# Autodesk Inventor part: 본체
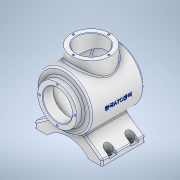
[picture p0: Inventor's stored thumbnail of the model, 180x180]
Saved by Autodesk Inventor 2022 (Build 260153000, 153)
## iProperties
Created: 2023-04
Part Number: 본체
Material: 알루미늄 6061
Document SubType Name: Modeling
Designer: Admin
Mass: 1291.94 g
Surface Area: 1063.05 cm^2
Volume: 478.495 cm^3
Density: 2.7 g/cm^3
Appearance: 알루미늄 - 평지
Author: Admin
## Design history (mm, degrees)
sketch "스케치2"
  geometry: L1 (-86.8, 0)-(86.8, 0) reference; L2 (0, -57.515)-(0, 99.419) reference; L3 (62, 0)-(62, 10); L4 (62, 10)-(23.355, 37.06); L5 (23.355, 37.06)-(23.355, 77); L6 (23.355, 77)-(-23.355, 77); L7 (-23.355, 77)-(-23.355, 37.06); L8 (-23.355, 37.06)-(-62, 10); L9 (-62, 10)-(-62, 0); L10 (-38.5, 0)-(38.5, 0); L11 (0, 0)-(0, 17); L12 (-62, 0)-(62, 0); A1 r 52.096 centre (0, -35.096) between (38.5, 0) and (-38.5, 0); 2 further points
  constraints: 20 end point, 4 symmetric about line, 3 perpendicular, 3 point on circle, 3 point on line, 1 centre point, 1 collinear, 1 horizontal, 1 midpoint, 1 parallel, 1 vertical
  dimensions: "d0" = 55 deg angle of L3 L4; "d1" = 10 distance of L3.start L3.end; "d2" = 124 distance between parallel lines of L3 L9; "d3" = 77 distance of L10.start L10.end; "d4" = 17 distance of L11.start L11.end; "d5" = 77 distance between parallel lines of L10 L6
extrude "돌출1" new body sketch "스케치2" stored distance "d6" = 80; taper "d7" = 0 deg
sketch "스케치3"
  geometry: L1 (77, 72.343)-(77, -93.292); L2 (0, -40)-(0, 40) reference; L3 (77, 48)-(127, 48); L4 (127, 48)-(127, -60); L5 (127, -60)-(77, -60); L6 (77, 48)-(77, -60); L7 (77, 40)-(37.06, 40) reference; L8 (-25.534, 0)-(153.205, 0) reference; L9 (77, 48)-(113, 48); L10 (113, 48)-(113, 60); L11 (113, 60)-(77, 60); L12 (77, 60)-(77, 48); L13 (0, 40)-(10, 40) reference; A1 r 113 centre (77, 53) between (77, -60) and (127, -48.336); 2 further points
  constraints: 18 end point, 4 point on line, 3 perpendicular, 2 horizontal, 2 parallel, 2 point on circle, 1 centre point, 1 collinear, 1 tangent, 1 vertical
  dimensions: "d8" = 77 distance between parallel lines of L2 L1; "d10" = 108 distance between parallel lines of L3 L5; "d12" = 226 diameter of A1; "d13" = 100 diameter of L4 L1; "d19" = 120 distance between parallel lines of L5 L11; "d20" = 72 diameter of L10 L1; "d21" = 20 distance between parallel lines of L13 L11
revolve "회전1" sketch "스케치3" stored, may be unused: angle "d14" = 360 deg
sketch "스케치6"
  geometry: L1 (77, 94.531)-(77, -106.028); L2 (0, -40)-(0, 40) reference; L3 (77, -53)-(120, -53); L4 (120, -53)-(120, 41); L5 (120, 41)-(77, 41); L6 (77, 41)-(77, -53); L7 (41, 60)-(113, 60) reference; L8 (77, 41)-(104, 41); L9 (104, 41)-(104, 60); L10 (104, 60)-(77, 60); L11 (77, 60)-(77, 41); A1 r 113 centre (77, 60) between (77, -53) and (120, -44.499); 3 further points
  constraints: 18 end point, 4 parallel, 3 point on line, 2 horizontal, 2 perpendicular, 2 point on circle, 1 centre point, 1 tangent, 1 vertical
  dimensions: "d22" = 77 distance between parallel lines of L2 L1; "d23" = 19 distance between parallel lines of L7 L5; "d24" = 54 diameter of L9.end L1; "d25" = 86 diameter of L4.end L1; "d27" = 113 distance between parallel lines of L7 L3; "d28" = 226 diameter of A1
revolve "회전2" sketch "스케치6" stored, may be unused: angle "d29" = 90 deg
node "작업 평면1"
sketch "스케치7"
  geometry: L1 (0, -57.6)-(0, 79.6) reference; L2 (50.4, 0)-(-50.4, 0) reference; L3 (-36, 60)-(36, 60) reference; C1 r 36 at (0, -2); 1 further point
  constraints: 1 centre point, 1 point on line
  dimensions: "d80" = 72 diameter of C1; "d81" = 62 distance from line of L3 C1.centre
extrude "돌출3" join sketch "스케치7" stored distance "d32" = 12; taper "d33" = 0 deg
sketch "스케치9"
  geometry: A1 r 32.5 centre (0, 0) between (0, 32.5) and (32.5, 0); 3 further points
  constraints: 4 point on circle, 1 centre point
  dimensions: "d37" = 65 diameter of A1
hole "구멍1" sketch "스케치9" at (0, 32.5), (32.5, 0), (0, -32.5), (-32.5, 0) diameter "d38" = 3.45873; stored, may be unused: countersink angle "d42" = 90 deg, drill point angle "d44" = 118 deg; dims "d39" = 8, "d40" = 4, "d41" = 2, "d43" = 10
node "작업 평면2"
sketch "스케치11"
  geometry: L1 (12.4, 0)-(-74.4, 0) reference; L2 (0, -56)-(0, 56) reference; L3 (-62, -40)-(-62, 40) reference; L4 (-62, 27)-(-54, 27); L5 (-54, 27)-(-54, 13); L6 (-54, 13)-(-62, 13); L7 (-62, 13)-(-62, 27); L8 (-62, -13)-(-54, -13); L9 (-54, -13)-(-54, -27); L10 (-54, -27)-(-62, -27); L11 (-62, -27)-(-62, -13); L12 (-62, -40)-(-38.5, -40) reference; 7 further points
  constraints: 16 end point, 4 parallel, 2 horizontal, 2 midpoint, 2 perpendicular, 2 point on line, 2 symmetric about line, 6 other
  dimensions: "d54" = 14 distance of L8.end L9.end; "d55" = 8 distance from line of L3 point (-54, -20); "d56" = 20 distance from line of L12 point (-54, -20)
extrude "돌출5" cut sketch "스케치11" distance "d57" = 20; taper "d58" = 0 deg
sketch "스케치14"
  geometry: L1 (-38.5, -96)-(-38.5, 16) reference; L2 (-125.3, -40)-(48.3, -40) reference; 5 further points
  constraints: 3 symmetric about line
  dimensions: "d59" = 108 distance of point (-92.5, -60) point (15.5, -60); "d60" = 40 distance of point (-92.5, -20) point (-92.5, -60)
hole "구멍3" sketch "스케치14" at (15.5, -60), (-92.5, -60), (15.5, -20), (-92.5, -20) diameter "d61" = 9; stored, may be unused: countersink angle "d65" = 90 deg, drill point angle "d67" = 0 deg; dims "d62" = 8, "d63" = 4, "d64" = 2, "d66" = 20
node "작업 평면3"
sketch "스케치15"
  geometry: L1 (41, 60)-(113, 60) reference; L2 (0, -40)-(0, 40) reference; 2 further points
  constraints: 1 other
  dimensions: "d69" = 62 distance from line of L1 point (77, -2); "d70" = 77 distance from line of L2 point (77, -2)
feature "엠보싱1" sketch "스케치15" dims "d8" = 77, "d10" = 108, "d12" = 226, "d13" = 100, "d19" = 120, "d20" = 72, "d21" = 20, "d71" = 0.5, "d72" = 0
fillet "모깎기1" dims "d73" = 3
chamfer "모따기1" distance "d74" = 1; stored, may be unused: second distance "d75" = 2, angle "d76" = 45 deg
fillet "모깎기2" dims "d77" = 3
fillet "모깎기3" dims "d78" = 3
fillet "모깎기4" dims "d79" = 3
sketch "스케치16"
  geometry: C1 r 27 at (0, 0); 1 further point
  constraints: 1 centre point
  dimensions: "d82" = 54 diameter of C1
extrude "돌출6" cut sketch "스케치16" distance "d83" = 40; taper "d84" = 0 deg
sketch "스케치17"
  geometry: A1 r 32.5 centre (0, 0) between (0, 32.5) and (32.5, 0); 3 further points
  constraints: 4 point on circle, 1 centre point
  dimensions: "d85" = 65 diameter of A1
hole "구멍4" sketch "스케치17" at (0, 32.5), (32.5, 0), (-32.5, 0), (0, -32.5) diameter "d86" = 3.45873; stored, may be unused: countersink angle "d90" = 90 deg, drill point angle "d92" = 118 deg; dims "d87" = 8, "d88" = 4, "d89" = 2, "d91" = 10
fillet "모깎기5" dims "d93" = 3
chamfer "모따기2" distance "d94" = 1; stored, may be unused: second distance "d95" = 2, angle "d96" = 45 deg
node "솔리드1"
mirror "미러1"
feature "A9D066F2-1C7D-4E18-AEED-F7BC21143FA4" dims "d61" = 9, "d62" = 8, "d63" = 4, "d64" = 2, "d65" = 90 deg, "d66" = 20, "d67" = 0
other parameters: "d30" = 142, "d53" = 6, "d68" = 69.75
